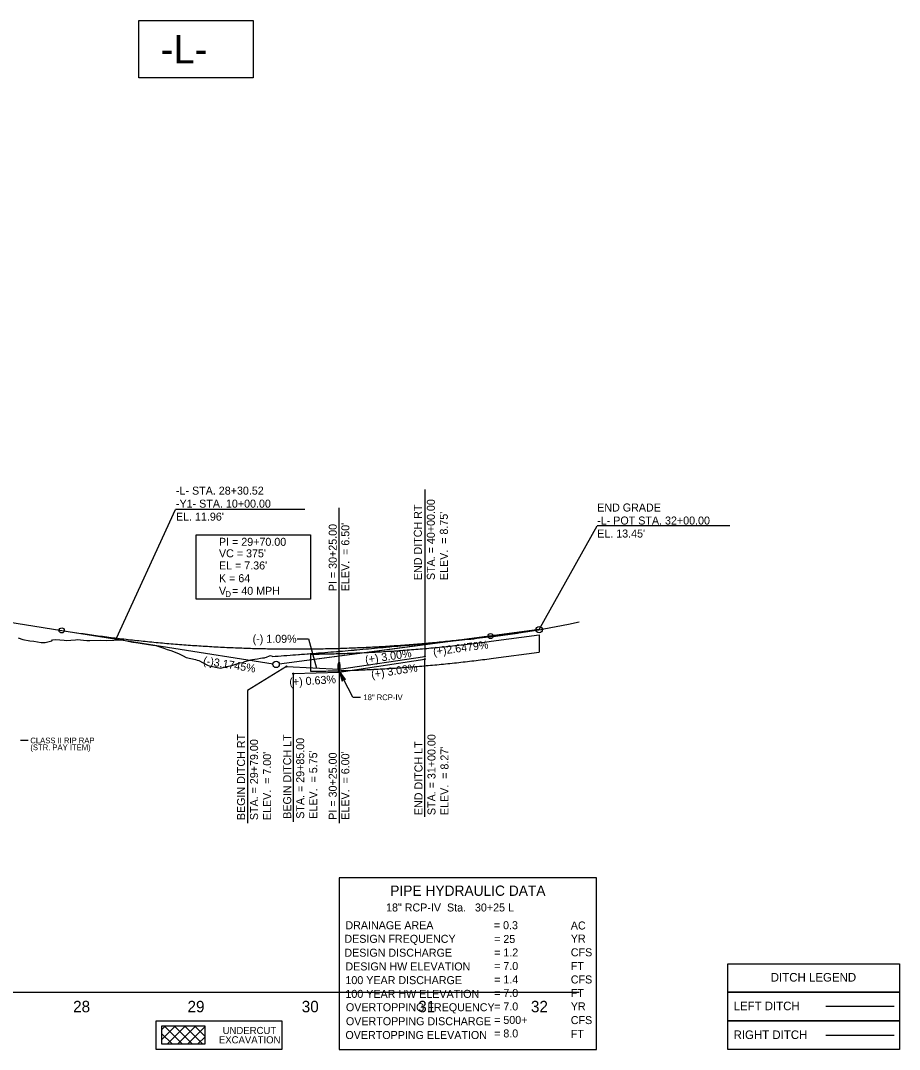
# Model space of a CAD drawing. Extents: x 1626634 to 1638383, y 876896 to 886347.
# Drawn here: x 1634460 to 1635229, y 883998 to 884898 of the extents above; entities that cross this region are included whole.
import ezdxf

# ---------------------------------------------------------------- set-up
doc = ezdxf.new("R2010")
doc.units = 0
for name, color, linetype in [('DTM Contours Minor', 7, 'Continuous'), ('DTM Contours Minor Text', 7, 'Continuous'), ('Exist Profile Cell', 7, 'Continuous'), ('Exist Vertical Profile Ground Line', 7, 'Continuous'), ('Exist Vertical Profile Horizontal Axis Label Major', 7, 'Continuous'), ('Old_Level_1', 7, 'Continuous'), ('Prop Shade Heavy', 7, 'Continuous'), ('Prop Shade Light', 7, 'Continuous'), ('Prop Vertical Profile Curve Label', 7, 'Continuous'), ('Prop Vertical Profile Grade', 7, 'Continuous'), ('Prop Vertical Profile Grade Label', 7, 'Continuous'), ('Prop VPI Label', 7, 'Continuous'), ('Scratch_Level_0', 7, 'Continuous'), ('Scratch_Level_3', 7, 'Continuous'), ('Sheet Block Revision CELL', 7, 'Continuous'), ('Sheet Block System Information CELL', 7, 'Continuous'), ('Sheet Block Title CELL', 7, 'Continuous'), ('Sheet Data Field CELL', 7, 'Continuous'), ('Sheet PE Seal Cell', 7, 'Continuous'), ('Sheet Plan And Profile CELL', 7, 'Continuous'), ('Sheet Profile CELL', 7, 'Continuous'), ('Stewart Logo', 7, 'Continuous'), ('Stewart Plot Border Xerox6279 and LJ5000', 7, 'Continuous')]:
    doc.layers.add(name, color=color, linetype=linetype)

msp = doc.modelspace()

# ---------------------------------------------------------------- linework, layer by layer
at = {"layer": 'DTM Contours Minor'}
for p, q in [((1634583.67, 884014.76), (1634586.73, 884017.82)), ((1634583.67, 884005.92), (1634595.57, 884017.82)), ((1634586.31, 884017.82), (1634601.72, 884002.4)), ((1634588.99, 884002.4), (1634604.41, 884017.82)), ((1634595.14, 884017.82), (1634610.56, 884002.4)), ((1634597.83, 884002.4), (1634613.25, 884017.82)), ((1634603.98, 884017.82), (1634619.4, 884002.4)), ((1634606.67, 884002.4), (1634621.8, 884017.53)), ((1634612.82, 884017.82), (1634621.8, 884008.83)), ((1634621.66, 884017.82), (1634621.8, 884017.67)), ((1634583.67, 884011.61), (1634592.88, 884002.4)), ((1634615.51, 884002.4), (1634621.8, 884008.69)), ((1634583.67, 884002.77), (1634584.04, 884002.4))]:
    msp.add_line(p, q, dxfattribs=at)
at = {"layer": 'Exist Profile Cell'}
msp.add_line((1632713.86, 884047.61), (1634948.96, 884047.61), dxfattribs=at)
at = {"layer": 'Exist Vertical Profile Ground Line'}
msp.add_lwpolyline([(1634458.36, 884357.54), (1634462.45, 884356.29), (1634468.37, 884355.11), (1634471.92, 884354.64), (1634478.39, 884353.68), (1634481.97, 884353.48), (1634487.69, 884355.14), (1634488.41, 884355.81), (1634490.88, 884356.18), (1634498.42, 884355.49), (1634500.35, 884355.43), (1634508.44, 884355.99), (1634509.83, 884356.05), (1634518.46, 884355.42), (1634519.31, 884355.4), (1634521.02, 884355.36), (1634530.02, 884355.5), (1634535.79, 884355.44), (1634548.24, 884355.89), (1634549.37, 884355.78), (1634558.59, 884353.8), (1634559.42, 884353.88), (1634576.17, 884351.31), (1634578.55, 884350.87), (1634585.64, 884348.74), (1634588.57, 884347.45), (1634591.85, 884346.64), (1634598.59, 884343.86), (1634602.47, 884341.97), (1634605.09, 884340.55), (1634613.23, 884338.65), (1634614.72, 884338.16), (1634616.35, 884337.92), (1634623.79, 884333.84), (1634625.21, 884333.19), (1634635.21, 884331.18), (1634640.76, 884332.49), (1634645.05, 884333.59), (1634652, 884335.65), (1634654.82, 884336.2), (1634656.63, 884337.04), (1634661.75, 884338.31), (1634662.61, 884338.48), (1634663.55, 884338.67), (1634665.16, 884338.93), (1634667.71, 884339.34), (1634670.27, 884339.75), (1634672.01, 884340.04), (1634672.82, 884340.17), (1634673.28, 884340.24), (1634673.71, 884340.3), (1634674.35, 884340.37), (1634675.37, 884340.78), (1634677.93, 884341.82), (1634678.84, 884342.19), (1634680.48, 884341.63), (1634681.05, 884341.43), (1634683.03, 884341.54), (1634683.39, 884341.56), (1634684.19, 884341.62), (1634685.59, 884341.72), (1634688.14, 884341.91), (1634690.69, 884342.1), (1634693.25, 884342.28), (1634696.09, 884342.49), (1634698.35, 884342.67), (1634700.91, 884342.88), (1634703.46, 884343.09), (1634704.18, 884343.14), (1634706.01, 884343.29), (1634708.57, 884343.48), (1634711.12, 884343.68), (1634712.2, 884343.76), (1634713.67, 884343.86), (1634716.23, 884344.04), (1634718.78, 884344.22), (1634720.39, 884344.33), (1634721.33, 884344.41), (1634723.89, 884344.63), (1634726.44, 884344.84), (1634728.99, 884345.06), (1634731.55, 884345.27), (1634733, 884345.39), (1634734.1, 884345.47), (1634736.65, 884345.65), (1634737.71, 884345.73), (1634739.21, 884345.87), (1634741.76, 884346.09), (1634744.31, 884346.32), (1634746.87, 884346.55), (1634749.42, 884346.78), (1634751.97, 884347), (1634752.77, 884347.07), (1634754.18, 884347.18), (1634754.53, 884347.21), (1634757.08, 884347.45), (1634759.63, 884347.7), (1634762.19, 884347.94), (1634764.74, 884348.17), (1634767.29, 884348.41), (1634769.85, 884348.65), (1634771.96, 884348.85), (1634772.46, 884348.88), (1634774.95, 884349.11), (1634777.51, 884349.34), (1634780.06, 884349.57), (1634782.62, 884349.8), (1634783.39, 884349.87), (1634785.17, 884350.02), (1634787.72, 884350.22), (1634790.28, 884350.43), (1634791.41, 884350.52), (1634792.01, 884350.57), (1634792.83, 884350.65), (1634795.38, 884350.88), (1634797.94, 884351.11), (1634800.49, 884351.33), (1634803.04, 884351.55), (1634805.6, 884351.77), (1634808.15, 884351.99), (1634810.77, 884352.21), (1634811.4, 884352.27), (1634813.26, 884352.47), (1634815.81, 884352.73), (1634818.36, 884352.99), (1634820.92, 884353.25), (1634823.47, 884353.5), (1634826.02, 884353.75), (1634828.58, 884354), (1634831.13, 884354.24), (1634832.9, 884354.41), (1634833.27, 884354.45), (1634833.68, 884354.5), (1634836.24, 884354.77), (1634838.79, 884355.05), (1634841.34, 884355.32), (1634843.9, 884355.59), (1634846.45, 884355.85), (1634849, 884356.11), (1634851.56, 884356.37), (1634854.11, 884356.63), (1634855, 884356.72), (1634855.37, 884356.77), (1634856.66, 884356.92), (1634859.22, 884357.23), (1634861.77, 884357.53), (1634864.32, 884357.82), (1634866.88, 884358.12), (1634869.43, 884358.41), (1634871.98, 884358.7), (1634875.01, 884359.05), (1634875.72, 884359.16), (1634895.04, 884361.83), (1634896.05, 884362), (1634917.23, 884365.37), (1634917.92, 884365.5), (1634939.49, 884369.61), (1634948.96, 884371.56)], dxfattribs=at)
at = {"layer": 'Old_Level_1'}
for p, q in [((1634813.86, 884487.27), (1634813.86, 884341.36)), ((1634738.86, 884330.11), (1634738.86, 884471.41)), ((1634702.13, 884356.78), (1634712.04, 884356.78)), ((1634712.04, 884356.78), (1634719.19, 884331.18)), ((1634692.86, 884332.61), (1634658.86, 884311.52)), ((1634658.86, 884311.52), (1634658.86, 884195.45))]:
    msp.add_line(p, q, dxfattribs=at)
for centre in [(1634813.86, 884341.36), (1634692.86, 884332.61), (1634738.86, 884330.11)]:
    msp.add_circle(centre, 0.5, dxfattribs=at)
at = {"layer": 'Prop Shade Heavy'}
for points in [[(1635078.86, 884072.61), (1635228.86, 884072.61), (1635228.86, 884047.61), (1635078.86, 884047.61)], [(1635078.86, 884047.61), (1635228.86, 884047.61), (1635228.86, 884022.61), (1635078.86, 884022.61)], [(1634578.86, 884022.61), (1634688.86, 884022.61), (1634688.86, 883997.61), (1634578.86, 883997.61)], [(1634583.67, 884002.4), (1634621.8, 884002.4), (1634621.8, 884017.82), (1634583.67, 884017.82)], [(1635078.86, 884022.61), (1635228.86, 884022.61), (1635228.86, 883997.61), (1635078.86, 883997.61)]]:
    msp.add_lwpolyline(points, close=True, dxfattribs=at)
at = {"layer": 'Prop Shade Light'}
msp.add_lwpolyline([(1634738.86, 883997.61), (1634963.86, 883997.61), (1634963.86, 884147.61), (1634738.86, 884147.61)], close=True, dxfattribs=at)
at = {"layer": 'Prop Vertical Profile Curve Label'}
for centre in [(1634496.36, 884364.14), (1634871.36, 884359.21)]:
    msp.add_circle(centre, 2.25, dxfattribs=at)
at = {"layer": 'Prop Vertical Profile Grade'}
for p, q in [((1634423.86, 884375.65), (1634496.36, 884364.14)), ((1634871.36, 884359.21), (1634913.86, 884364.83))]:
    msp.add_line(p, q, dxfattribs=at)
msp.add_spline([(1634496.36, 884364.14), (1634503.86, 884362.98), (1634511.36, 884361.85), (1634518.86, 884360.77), (1634526.36, 884359.73), (1634533.86, 884358.74), (1634541.36, 884357.79), (1634548.86, 884356.88), (1634556.36, 884356.02), (1634563.86, 884355.2), (1634571.36, 884354.42), (1634578.86, 884353.69), (1634586.36, 884353), (1634593.86, 884352.36), (1634601.36, 884351.76), (1634608.86, 884351.2), (1634616.36, 884350.69), (1634623.86, 884350.22), (1634631.36, 884349.79), (1634638.86, 884349.41), (1634646.36, 884349.07), (1634653.86, 884348.77), (1634661.36, 884348.52), (1634668.86, 884348.31), (1634676.36, 884348.15), (1634683.86, 884348.03), (1634691.36, 884347.95), (1634698.86, 884347.92), (1634706.36, 884347.93), (1634713.86, 884347.98), (1634721.36, 884348.08), (1634728.86, 884348.22), (1634736.36, 884348.41), (1634743.86, 884348.64), (1634751.36, 884348.91), (1634758.86, 884349.23), (1634766.36, 884349.58), (1634773.86, 884349.99), (1634781.36, 884350.44), (1634788.86, 884350.93), (1634796.36, 884351.46), (1634803.86, 884352.04), (1634811.36, 884352.66), (1634818.86, 884353.33), (1634826.36, 884354.04), (1634833.86, 884354.79), (1634841.36, 884355.58), (1634848.86, 884356.42), (1634856.36, 884357.31), (1634863.86, 884358.24), (1634871.36, 884359.21)], degree=3, dxfattribs=at)
at = {"layer": 'Prop VPI Label'}
for p, q in [((1634544.38, 884357.42), (1634595.84, 884469.94)), ((1634708.95, 884469.94), (1634595.84, 884469.94)), ((1634913.86, 884364.81), (1634964.61, 884455.51)), ((1635080.48, 884455.51), (1634964.61, 884455.51)), ((1634496.36, 884364.14), (1634681.15, 884334.81)), ((1634913.86, 884364.83), (1634686.59, 884334.74)), ((1634871.36, 884359.21), (1634686.59, 884334.74))]:
    msp.add_line(p, q, dxfattribs=at)
for points in [[(1634563.84, 884897.61), (1634663.84, 884897.61), (1634663.84, 884847.61), (1634563.84, 884847.61)], [(1634563.84, 884897.61), (1634663.84, 884897.61), (1634663.84, 884847.61), (1634563.84, 884847.61)], [(1634563.84, 884897.61), (1634663.84, 884897.61), (1634663.84, 884847.61), (1634563.84, 884847.61)], [(1634563.84, 884897.61), (1634663.84, 884897.61), (1634663.84, 884847.61), (1634563.84, 884847.61)], [(1634613.86, 884447.61), (1634713.86, 884447.61), (1634713.86, 884391.43), (1634613.86, 884391.43)], [(1634613.86, 884447.61), (1634713.86, 884447.61), (1634713.86, 884391.43), (1634613.86, 884391.43)]]:
    msp.add_lwpolyline(points, close=True, dxfattribs=at)
for centre in [(1634913.86, 884364.83), (1634913.86, 884364.83), (1634913.86, 884364.83), (1634683.86, 884334.38)]:
    msp.add_circle(centre, 2.75, dxfattribs=at)
at = {"layer": 'Scratch_Level_0'}
for p, q in [((1634813.86, 884200.97), (1634813.86, 884338.96)), ((1634698.86, 884326.36), (1634698.86, 884196.7)), ((1634738.86, 884327.61), (1634738.86, 884195.45))]:
    msp.add_line(p, q, dxfattribs=at)
for centre in [(1634813.86, 884338.96), (1634698.86, 884326.36), (1634738.86, 884327.61)]:
    msp.add_circle(centre, 0.5, dxfattribs=at)
at = {"layer": 'Scratch_Level_3'}
for p, q in [((1634871.96, 884354.66), (1634913.86, 884360.21)), ((1634913.86, 884360.21), (1634913.86, 884345.08)), ((1634713.86, 884343.4), (1634713.86, 884328.4)), ((1634713.86, 884343.4), (1634713.86, 884328.4)), ((1634873.93, 884339.79), (1634913.86, 884345.08))]:
    msp.add_line(p, q, dxfattribs=at)
for points in [[(1634713.86, 884343.4), (1634713.91, 884343.4), (1634721.44, 884343.5), (1634728.96, 884343.64), (1634736.49, 884343.83), (1634744.02, 884344.06), (1634751.54, 884344.33), (1634759.07, 884344.65), (1634766.6, 884345.01), (1634774.12, 884345.41), (1634781.65, 884345.86), (1634789.18, 884346.35), (1634796.7, 884346.89), (1634804.23, 884347.47), (1634811.76, 884348.09), (1634819.28, 884348.76), (1634826.81, 884349.47), (1634834.33, 884350.23), (1634841.86, 884351.03), (1634849.39, 884351.87), (1634856.91, 884352.76), (1634864.44, 884353.69), (1634871.96, 884354.66)], [(1634713.86, 884328.4), (1634714.06, 884328.4), (1634721.68, 884328.5), (1634729.29, 884328.64), (1634736.9, 884328.83), (1634744.52, 884329.06), (1634752.13, 884329.34), (1634759.74, 884329.66), (1634767.36, 884330.03), (1634774.97, 884330.44), (1634782.59, 884330.89), (1634790.2, 884331.39), (1634797.81, 884331.93), (1634805.42, 884332.52), (1634813.04, 884333.15), (1634820.65, 884333.82), (1634828.26, 884334.54), (1634835.88, 884335.31), (1634843.49, 884336.12), (1634851.1, 884336.97), (1634858.71, 884337.87), (1634866.32, 884338.81), (1634873.93, 884339.79)]]:
    msp.add_spline(points, degree=3, dxfattribs=at)
at = {"layer": 'Sheet Block Revision CELL'}
msp.add_line((1634544.27, 884356.39), (1634544.27, 884355.75), dxfattribs=at)
at = {"layer": 'Sheet Block Title CELL'}
msp.add_lwpolyline([(1634744.62, 884321.24), (1634738.86, 884328.81), (1634741.73, 884319.68), (1634742.66, 884321.51)], close=True, dxfattribs=at)
at = {"layer": 'Sheet Data Field CELL'}
for p, q in [((1634750.87, 884305.72), (1634738.86, 884328.81)), ((1634750.87, 884305.72), (1634757.61, 884305.72)), ((1634467.16, 884267.95), (1634460.41, 884267.95))]:
    msp.add_line(p, q, dxfattribs=at)
at = {"layer": 'Sheet PE Seal Cell'}
for p, q in [((1635164.41, 884035.31), (1635224.41, 884035.31)), ((1635078.86, 884007.61), (1635078.86, 884007.61)), ((1635164.41, 884009.96), (1635224.41, 884009.96))]:
    msp.add_line(p, q, dxfattribs=at)
at = {"layer": 'Sheet Plan And Profile CELL'}
msp.add_lwpolyline([(1634692.86, 884332.61), (1634738.86, 884330.11), (1634813.86, 884341.36)], dxfattribs=at)
at = {"layer": 'Stewart Logo'}
msp.add_ellipse((1634738.86, 884332.56), major_axis=(0, -3.75), ratio=0.2, dxfattribs=at)
at = {"layer": 'Stewart Plot Border Xerox6279 and LJ5000'}
msp.add_lwpolyline([(1634698.86, 884326.36), (1634738.86, 884327.61), (1634813.86, 884338.96)], dxfattribs=at)

# ---------------------------------------------------------------- texts
at = {"layer": 'DTM Contours Minor Text'}
for s, p in [('UNDERCUT', (1634637.06, 884011.08)), ('EXCAVATION', (1634633.78, 884002.89))]:
    msp.add_text(s, height=6.25, dxfattribs=at).set_placement(p)
at = {"layer": 'Exist Vertical Profile Horizontal Axis Label Major'}
for s, p in [('28', (1634506.33, 884030.11)), ('29', (1634606.37, 884030.11)), ('30', (1634706.25, 884030.11)), ('31', (1634808.09, 884030.11)), ('32', (1634906.64, 884030.11))]:
    msp.add_text(s, height=10, dxfattribs=at).set_placement(p)
at = {"layer": 'Old_Level_1'}
for s, p in [('STA. = 40+00.00', (1634822.65, 884408.18)), ('END DITCH RT', (1634811.27, 884408.18)), ("ELEV.  = 8.75'", (1634834.02, 884408.18)), ("ELEV.  = 6.50'", (1634747.86, 884398.46)), ('PI = 30+25.00', (1634736.86, 884398.46)), ('BEGIN DITCH RT', (1634656.68, 884198.19)), ('STA. = 29+79.00', (1634668.06, 884198.19)), ("ELEV.  = 7.00'", (1634679.43, 884198.19))]:
    msp.add_text(s, height=7, rotation=90, dxfattribs=at).set_placement(p)
at = {"layer": 'Prop Shade Light'}
for s, height, p in [('PIPE HYDRAULIC DATA', 8.9997, (1634783.66, 884131.96)), (' 18" RCP-IV  Sta.   30+25 L ', 6.9996, (1634777.4, 884118.28)), ('DRAINAGE AREA', 6.9999, (1634744.44, 884102.71)), ('= 0.3    ', 7, (1634874.23, 884102.79)), ('AC', 7, (1634941.53, 884102.51)), ('DESIGN FREQUENCY', 6.9999, (1634743.54, 884090.86)), ('= 25 ', 7, (1634874.47, 884090.71)), ('YR', 7, (1634941.53, 884091.11)), ('DESIGN DISCHARGE', 6.9999, (1634743.54, 884078.71)), ('= 1.2     ', 7, (1634874.47, 884078.91)), ('CFS', 7, (1634941.53, 884079.06)), ('DESIGN HW ELEVATION', 6.9999, (1634744.44, 884066.71)), ('= 7.0     ', 7, (1634874.47, 884067.11)), ('FT', 7, (1634941.53, 884067.11)), ('100 YEAR DISCHARGE', 6.9999, (1634744.44, 884054.71)), ('= 1.4     ', 7, (1634874.47, 884055.31)), ('CFS', 7, (1634941.53, 884055.31)), ('100 YEAR HW ELEVATION', 6.9999, (1634744.44, 884042.71)), ('= 7.0     ', 7, (1634874.47, 884043.51)), ('FT', 7, (1634941.53, 884043.51)), ('OVERTOPPING FREQUENCY', 6.9999, (1634744.89, 884031.01)), ('= 7.0 ', 7, (1634874.47, 884031.71)), ('YR', 7, (1634941.53, 884031.81)), ('OVERTOPPING DISCHARGE', 6.9999, (1634744.89, 884018.76)), ('= 500+    ', 7, (1634874.47, 884019.91)), ('CFS', 7, (1634941.53, 884019.76)), ('OVERTOPPING ELEVATION', 6.9999, (1634744.44, 884006.71)), ('= 8.0     ', 7, (1634874.47, 884008.11)), ('FT', 7, (1634941.53, 884007.71))]:
    msp.add_text(s, height=height, dxfattribs=at).set_placement(p)
at = {"layer": 'Prop Vertical Profile Curve Label'}
for s, height, p in [('-L-', 25, (1634582.98, 884860.11)), ("VC = 375'", 7, (1634633.87, 884428.1)), ('K = 64', 7, (1634633.87, 884406.31))]:
    msp.add_text(s, height=height, dxfattribs=at).set_placement(p)
for s, height, p in [('V  = 40 MPH', 7, (1634633.87, 884395.27)), ('D', 5.25, (1634639.37, 884393.27))]:
    msp.add_text(s, height=height, rotation=360, dxfattribs=at).set_placement(p)
at = {"layer": 'Prop Vertical Profile Grade Label'}
for s, rotation, p in [('(+)2.6479%', 7.54173, (1634821.57, 884342.09)), ('(-)3.1745%', 350.98101, (1634619.66, 884334.45))]:
    msp.add_text(s, height=7, rotation=rotation, dxfattribs=at).set_placement(p)
at = {"layer": 'Prop VPI Label'}
for s, p in [('-L- STA. 28+30.52', (1634596.28, 884482.92)), ('-Y1- STA. 10+00.00', (1634596.28, 884471.54)), ('END GRADE', (1634964.61, 884468.14)), ("EL. 11.96'", (1634596.28, 884460.17)), ('-L- POT STA. 32+00.00', (1634964.61, 884456.76)), ("EL. 13.45'", (1634964.61, 884445.39)), ('PI = 29+70.00', (1634633.87, 884438.14)), ("EL = 7.36'", (1634633.87, 884417.48))]:
    msp.add_text(s, height=7, dxfattribs=at).set_placement(p)
at = {"layer": 'Scratch_Level_0'}
for s, p in [('BEGIN DITCH LT', (1634697.04, 884199.4)), ('STA. = 29+85.00', (1634708.41, 884199.4)), ('STA. = 31+00.00', (1634823.21, 884202.58)), ('END DITCH LT', (1634811.83, 884202.58)), ("ELEV.  = 8.27'", (1634834.58, 884202.58)), ("ELEV.  = 5.75'", (1634719.79, 884199.4)), ('PI = 30+25.00', (1634736.86, 884198.53)), ("ELEV.  = 6.00'", (1634747.86, 884198.53))]:
    msp.add_text(s, height=7, rotation=90, dxfattribs=at).set_placement(p)
at = {"layer": 'Sheet Block System Information CELL'}
for s, rotation, p in [('(+) 3.03%', 8.60546, (1634767.47, 884322.17)), ('(+) 0.63%', 3.57633, (1634695.59, 884315.46))]:
    msp.add_text(s, height=7, rotation=rotation, dxfattribs=at).set_placement(p)
at = {"layer": 'Sheet Data Field CELL'}
for s, p in [('18" RCP-IV', (1634760.17, 884303.13)), ('CLASS II RIP RAP', (1634468.95, 884265.36)), ('(STR. PAY ITEM)', (1634468.95, 884259.36))]:
    msp.add_text(s, height=5, dxfattribs=at).set_placement(p)
at = {"layer": 'Sheet PE Seal Cell'}
for s, height, p in [('DITCH LEGEND', 7.5, (1635116.36, 884056.96)), ('LEFT DITCH', 7.485, (1635083.86, 884031.91)), ('RIGHT DITCH', 7.485, (1635083.86, 884006.71))]:
    msp.add_text(s, height=height, dxfattribs=at).set_placement(p)
at = {"layer": 'Sheet Profile CELL'}
msp.add_text('(-) 1.09%', height=7, dxfattribs=at).set_placement((1634663.28, 884353.31))
msp.add_text('(+) 3.00%', height=7, rotation=8.23231, dxfattribs=at).set_placement((1634762.18, 884335.04))

doc.saveas('drawing.dxf')
